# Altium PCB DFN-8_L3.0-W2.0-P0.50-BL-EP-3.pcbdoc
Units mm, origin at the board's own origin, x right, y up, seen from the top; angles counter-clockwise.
Board outline 14.85 x 16.55 mm, 2 copper layers (Top Layer, Bottom Layer), stack 0 mm thick; 1 components, 0 nets, 9 pads, 0 vias.
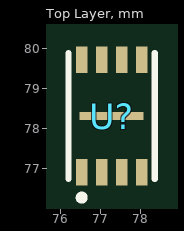
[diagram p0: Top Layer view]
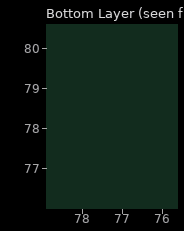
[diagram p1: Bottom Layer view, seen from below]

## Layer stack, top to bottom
Top Layer: signal copper (thickness not stored)
Bottom Layer: signal copper (thickness not stored)

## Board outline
84.702,69.85 69.85,69.85 69.85,86.405 84.702,86.405

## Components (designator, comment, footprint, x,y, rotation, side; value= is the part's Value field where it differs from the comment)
U? "" DFN-8_L3.0-W2.0-P0.50-BL-EP-3 77.276,78.315 r0 top

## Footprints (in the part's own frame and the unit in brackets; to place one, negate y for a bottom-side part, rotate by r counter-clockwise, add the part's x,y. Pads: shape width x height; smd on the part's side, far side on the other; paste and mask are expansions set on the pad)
DFN-8_L3.0-W2.0-P0.50-BL-EP-3 [mm]
  rect 0.28x0.665 smd paste+0 mask+0.05: 1(-0.75,-1.407) 2(-0.25,-1.407) 3(0.25,-1.407) 4(0.75,-1.407) 5(0.75,1.407) 6(0.25,1.407) 7(-0.25,1.407) 8(-0.75,1.407)
  rect 1.6x0.2 smd: 9(0,0)
  silkscreen extent -1.08,-2.11 1.08,1.58

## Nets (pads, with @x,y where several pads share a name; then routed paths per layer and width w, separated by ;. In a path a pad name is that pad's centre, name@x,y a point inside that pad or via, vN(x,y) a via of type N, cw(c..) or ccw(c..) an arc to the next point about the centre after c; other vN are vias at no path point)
pads on no net: U?.1 U?.2 U?.3 U?.4 U?.5 U?.6 U?.7 U?.8 U?.9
